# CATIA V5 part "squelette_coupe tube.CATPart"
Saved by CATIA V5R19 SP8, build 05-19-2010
Part number: squelette_coupe tube
Publications: "Rt", "R8", "R11", "R9", "e", "Centre_roulette_chanfreinage", "H", "V", "X", "Z", "Y", "Axe_vis", "Début", "Fin", "Point.2", "Distance", "suport_axe_rouleau", "Début1", "Fin1", "Angle", "centre_roulette_coupe", "Distance1", "centre_rouleau", "Distance2", "roulette_chanfreinage", "rouleau", "roulette_coupe", "centre_tube", "H1", "V1", "X1", "Y1", "Z1", "tube"
Bounding box of the stored display mesh (mm): x 0 to 0, y -20 to 20, z -100 to 20
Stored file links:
  G:\EU_thinkMotion\CFAO_2010\MMS_groupe3\MMS_groupe3\A reprendre\ftixier\florent-tixier\florent-tixier\squelette_coupe tube.CATPart
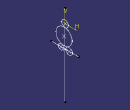
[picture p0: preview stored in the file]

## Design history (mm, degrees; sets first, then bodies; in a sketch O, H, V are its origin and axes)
Parameters
  Rt = 12 mm
  R8 = 5 mm
  R11 = 5 mm
  R9 = 4 mm
  e = 12 mm
Body1 (main body)
  Point1 "Centre_roulette_chanfreinage": type OnPlane, Support xy-plane, H 0, V 0, Direction (1, 0, 0)
  Line1 "Axe_vis": type Normal, RefPoint Point1, RefSkin xy-plane, Start -100, End 20
  Point2: type OnCurve, Support Line1, RefPoint Point1, Length 32.3031 {= (sqrt((((R8 +Rt )*(R8 +Rt )))-(((R11 -R9 )*(R11 +R9 +2*Rt ))*((R11 -R9 )*(R11 +R9 +2*Rt ))/(16*e *e ))))+(sqrt((((R9 +Rt )*(R9 +Rt )))-((((R9 -R11 )*(R11 +R9 +2*Rt ))+e*e)*(((R9 -R11 )*(R11 +R9 +2*Rt ))+e*e)/(4*e *e ))))}
  Line2 "suport_axe_rouleau": type Angle, RefPoint Point2, Curve Line1, Support yz-plane, Start -20, End 20, Angle 90
  Point3 "centre_roulette_coupe": type OnCurve, Support Line2, RefPoint Point2, Length 6 {= e /2}
  Point4 "centre_rouleau": type OnCurve, Support Line2, RefPoint Point2, Length 6 {= e /2}
  Sketch1 "roulette_chanfreinage" on yz-plane, origin (0, 0, 0), H (0, 1, 0), V (0, 0, 1)
    circle A1 centre (0, 0) radius 5
    radius A1 = 5 {= R8}
  Sketch2 "rouleau" on yz-plane, origin (0, 0, 0), H (0, 1, 0), V (0, 0, 1)
    circle A1 centre (6, -32.3031) radius 5
    reference projected point E1 (6, -32.3031) from Point4
    radius A1 = 5 {= R11}
    concentricity: A1 E1
  Sketch3 "roulette_coupe" on yz-plane, origin (0, 0, 0), H (0, 1, 0), V (0, 0, 1)
    circle A1 centre (-6, -32.3031) radius 4
    reference projected point E1 (-6, -32.3031) from Point3
    radius A1 = 4 {= R9}
    concentricity: A1 E1
  Point5 "centre_tube": type OnPlane, Support yz-plane, H -1.375 {= -((R11 -R9 )*(R11 +R9 +2*Rt ))/(2*e )}, V -16.9443 {= -sqrt((((R8 +Rt )*(R8 +Rt )))-(((R11 -R9 )*(R11 +R9 +2*Rt ))*((R11 -R9 )*(R11 +R9 +2*Rt ))/(4*e *e )))}, Direction (0, 1, 0)
  Sketch4 "tube" on yz-plane, origin (0, 0, 0), H (0, 1, 0), V (0, 0, 1)
    circle A1 centre (-1.375, -16.9443) radius 12
    reference projected point E1 (-1.375, -16.9443) from Point5
    radius A1 = 12 {= Rt}
    concentricity: A1 E1
Relations
  Point5.V = -sqrt(((`rayon_tube` +`rayon_roulette_chanfreinage` )*(`rayon_tube` +`rayon_roulette_chanfreinage` )-((`entraxe_rouleau_roulette_coupe` *`entraxe_rouleau_roulette_coupe` +`rayon_rouleau` *`rayon_rouleau` -`rayon_roulette_coupe` *`rayon_roulette_coupe` +2*`rayon_tube` *(`rayon_rouleau` -`rayon_roulette_coupe` ))/(2*`entraxe_rouleau_roulette_coupe` )-`entraxe_rouleau_roulette_coupe` )*((`entraxe_rouleau_roulette_coupe` *`entraxe_rouleau_roulette_coupe` +`rayon_rouleau` *`rayon_rouleau` -`rayon_roulette_coupe` *`rayon_roulette_coupe` +2*`rayon_tube` *(`rayon_rouleau` -`rayon_roulette_coupe` ))/(2*`entraxe_rouleau_roulette_coupe` )-`entraxe_rouleau_roulette_coupe` ))/1mm))*1mm (deactivated)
